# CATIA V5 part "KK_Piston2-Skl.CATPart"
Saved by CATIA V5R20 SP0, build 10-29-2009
Part number: Piston2-Skl
Bounding box of the stored display mesh (mm): x 20 to 49.705, y 61.671 to 86.772, z 0 to 100
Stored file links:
  G:\Khaled_CFAO_2011\ST2M\ST2M_GR1\msallin\Khaled\Version_Finale\KK_Piston2-Skl.CATPart
  C:\Users\Mathieu\Desktop\Think Motion\JOUG-MELEE2.CATProduct
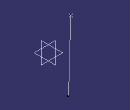
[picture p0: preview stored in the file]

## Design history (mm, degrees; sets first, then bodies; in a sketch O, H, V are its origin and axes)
External parameters (linked from other documents)
  `External.Taille du joug` = 100 mm
Set1
  Point1: linked copy from another document
  Point2: linked copy from another document
Set2
  Line1: type PtPt, FirstPoint Point1, SecondPoint Point2
  Point3: (0, 0, 0), relative to Point1
Body1 (main body)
